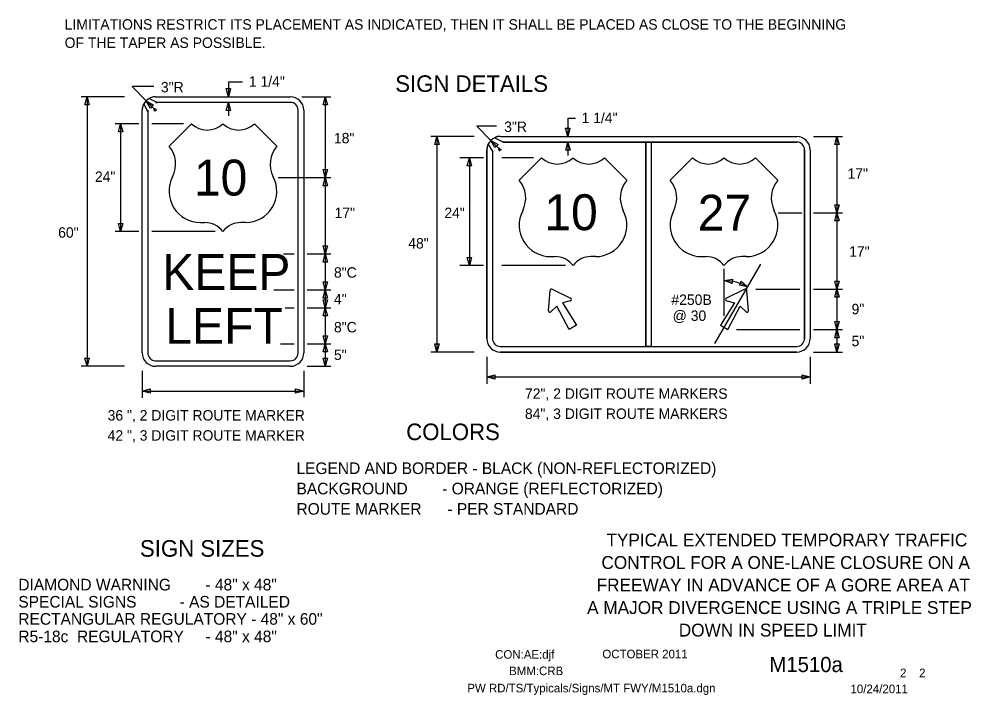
# Model space of a CAD drawing. Extents: x 16335 to 18464, y 5417 to 6974.
# Drawn here: x 17775 to 18464, y 5932 to 6421 of the extents above; entities that cross this region are included whole.
import ezdxf

# ---------------------------------------------------------------- set-up
doc = ezdxf.new("R2010")
doc.units = 0
for name, color, linetype in [('BORDER', 7, 'Continuous'), ('BORDER_SIGNAL_WO', 7, 'Continuous'), ('TRAFFIC_SIGNS_PR', 7, 'Continuous'), ('TYPICAL_EX', 7, 'Continuous'), ('TYPICAL_TEXT_DIMEN_PR', 7, 'Continuous')]:
    doc.layers.add(name, color=color, linetype=linetype)

msp = doc.modelspace()

# ---------------------------------------------------------------- linework, layer by layer
at = {"layer": 'TRAFFIC_SIGNS_PR'}
for p, q in [((17866.33, 6360.97), (17865.33, 6359.46)), ((17875.12, 6360.53), (17869.02, 6363.27)), ((17873.92, 6364.59), (17971.42, 6364.59)), ((17971.42, 6360.53), (17873.92, 6360.53)), ((17864.17, 6179.34), (17864.17, 6354.84)), ((17865.36, 6359.39), (17868.23, 6353.35)), ((17868.23, 6354.84), (17868.23, 6179.34)), ((17977.1, 6179.34), (17977.1, 6354.84)), ((17981.17, 6354.84), (17981.17, 6179.34)), ((18125.39, 6331.84), (18119.16, 6334.86)), ((18123.44, 6335.89), (18337.94, 6335.89)), ((18123.44, 6335.89), (18337.94, 6335.89)), ((18113.69, 6326.14), (18113.69, 6189.64)), ((18113.69, 6189.64), (18113.69, 6326.14)), ((18114.61, 6330.15), (18117.74, 6325.11)), ((18117.75, 6325.09), (18117.75, 6189.64)), ((18117.75, 6325.09), (18117.75, 6189.64)), ((18125.38, 6331.83), (18228.66, 6331.83)), ((18337.94, 6331.83), (18125.38, 6331.83)), ((18228.66, 6331.83), (18228.66, 6183.95)), ((18232.72, 6331.83), (18232.72, 6183.95)), ((18232.72, 6331.83), (18337.94, 6331.83)), ((18343.62, 6326.14), (18343.62, 6280.39)), ((18343.63, 6189.64), (18343.63, 6326.14)), ((18347.69, 6326.14), (18347.69, 6189.64)), ((18347.69, 6326.14), (18347.69, 6189.64)), ((18343.62, 6280.39), (18343.62, 6189.64)), ((18158.29, 6209.75), (18159.44, 6224.47)), ((18160.95, 6225.34), (18174.27, 6218.98)), ((18300.42, 6225.34), (18287.11, 6218.98)), ((18303.08, 6209.75), (18301.94, 6224.47)), ((18123.44, 6183.95), (18337.94, 6183.95)), ((17873.92, 6173.65), (17971.42, 6173.65)), ((18123.44, 6179.89), (18337.94, 6179.89)), ((18337.94, 6179.89), (18123.44, 6179.89)), ((17971.42, 6169.59), (17873.92, 6169.59))]:
    msp.add_line(p, q, dxfattribs=at)
for points in [[(18117.74, 6325.11), (18117.75, 6325.09)], [(18125.38, 6331.83), (18125.36, 6331.84)], [(18174.1, 6217.01), (18168.38, 6215.43), (18178.6, 6199.26), (18173.2, 6196.14), (18164.31, 6213.08), (18160.08, 6208.91)], [(18287.27, 6217.01), (18292.99, 6215.43), (18282.78, 6199.26), (18288.17, 6196.14), (18297.07, 6213.08), (18301.29, 6208.91)]]:
    msp.add_lwpolyline(points, dxfattribs=at)
msp.add_lwpolyline([(18228.66, 6331.83), (18232.72, 6331.83), (18232.72, 6183.95), (18228.66, 6183.95)], close=True, dxfattribs=at)
for centre, radius, start, end in [((17873.92, 6354.84), 9.75, 90, 180), ((17873.33, 6357.01), 7.6, 85.58319, 124.53531), ((17874.52, 6364.95), 4.47, 262.2432, 277.7568), ((17971.42, 6354.84), 9.75, 0, 90), ((17971.42, 6354.84), 5.69, 0, 90), ((17871.2, 6355.43), 7.06, 145.86811, 184.82317), ((17862.77, 6354.1), 5.51, 352.24294, 7.75653), ((18123.44, 6326.14), 9.75, 90, 180), ((18123.44, 6326.14), 9.75, 90, 180), ((18122.76, 6329.33), 6.6, 84.11162, 123.06374), ((18337.94, 6326.14), 9.75, 0, 90), ((18337.94, 6326.14), 9.75, 0, 90), ((18119.82, 6326.85), 6.17, 147.60925, 186.56283), ((18124.38, 6339.01), 7.24, 277.81035, 278.05403), ((18337.94, 6326.14), 5.69, 0, 89.99421), ((18337.94, 6326.14), 5.69, 0, 90), ((18160.5, 6224.38), 1.06, 64.48226, 175.51774), ((18300.88, 6224.38), 1.06, 4.48226, 115.51774), ((18173.81, 6218.02), 1.06, 285.9885, 64.48226), ((18287.56, 6218.02), 1.06, 115.51774, 254.0115), ((18159.35, 6209.67), 1.06, 175.51775, 314.01151), ((18302.03, 6209.67), 1.06, 225.98849, 4.48225), ((18123.44, 6189.64), 9.75, 180, 270), ((18123.44, 6189.64), 9.75, 180, 270), ((18123.44, 6189.64), 5.69, 180, 270), ((18123.44, 6189.64), 5.69, 180, 270), ((18337.94, 6189.64), 9.75, 270, 0), ((18337.94, 6189.64), 5.69, 270, 0), ((18337.94, 6189.64), 9.75, 270, 0), ((18337.94, 6189.64), 5.69, 270, 0), ((17873.92, 6179.34), 9.75, 180, 270), ((17873.92, 6179.34), 5.69, 180, 270), ((17971.42, 6179.34), 5.69, 270, 0), ((17971.42, 6179.34), 9.75, 270, 0)]:
    msp.add_arc(centre, radius, start, end, dxfattribs=at)
at = {"layer": 'TYPICAL_EX'}
for p, q in [((17883.67, 6328.84), (17899.92, 6345.09)), ((17961.67, 6328.84), (17945.42, 6345.09)), ((18137.05, 6304.23), (18153.3, 6320.48)), ((18215.05, 6304.23), (18198.8, 6320.48)), ((18246.33, 6304.23), (18262.58, 6320.48)), ((18324.33, 6304.23), (18308.08, 6320.48)), ((17906.39, 6273.55), (17909.64, 6273.55)), ((17938.94, 6273.55), (17935.69, 6273.55)), ((18159.78, 6248.94), (18163.03, 6248.94)), ((18192.32, 6248.94), (18189.07, 6248.94)), ((18269.05, 6248.94), (18272.3, 6248.94)), ((18301.6, 6248.94), (18298.35, 6248.94))]:
    msp.add_line(p, q, dxfattribs=at)
for centre, radius, start, end in [((17911.29, 6356.93), 16.42, 226.14041, 313.85958), ((17934.04, 6356.93), 16.42, 226.14042, 313.85959), ((17868.26, 6315.83), 20.16, 333.09768, 40.19361), ((17977.07, 6315.83), 20.16, 139.80639, 206.90233), ((18164.68, 6332.32), 16.42, 226.14041, 313.85958), ((18187.42, 6332.32), 16.42, 226.14042, 313.85959), ((18273.95, 6332.32), 16.42, 226.14041, 313.85958), ((18296.7, 6332.32), 16.42, 226.14042, 313.85959), ((17906.43, 6296.27), 22.73, 152.6698, 269.90132), ((17938.9, 6296.27), 22.73, 270.09868, 27.3302), ((18121.65, 6291.22), 20.16, 333.09768, 40.19361), ((18230.45, 6291.22), 20.16, 139.80639, 206.90233), ((18230.93, 6291.22), 20.16, 333.09768, 40.19361), ((18339.73, 6291.22), 20.16, 139.80639, 206.90233), ((18159.82, 6271.66), 22.73, 152.6698, 269.90132), ((18192.28, 6271.66), 22.73, 270.09868, 27.3302), ((18269.09, 6271.66), 22.73, 152.6698, 269.90132), ((18301.56, 6271.66), 22.73, 270.09868, 27.3302), ((17909.68, 6257.27), 16.28, 37.1038, 90.13853), ((17935.65, 6257.27), 16.28, 89.86147, 142.8962), ((18163.07, 6232.66), 16.28, 37.1038, 90.13853), ((18189.03, 6232.66), 16.28, 89.86147, 142.8962), ((18272.35, 6232.66), 16.28, 37.1038, 90.13853), ((18298.31, 6232.66), 16.28, 89.86147, 142.8962)]:
    msp.add_arc(centre, radius, start, end, dxfattribs=at)
at = {"layer": 'TYPICAL_TEXT_DIMEN_PR'}
for p, q in [((17926.64, 6375.35), (17926.64, 6364.59)), ((17926.64, 6375.35), (17936.74, 6375.35)), ((17872.54, 6371.87), (17856.88, 6371.87)), ((17856.88, 6371.87), (17867.12, 6361.64)), ((17926.64, 6364.59), (17925.07, 6370.45)), ((17925.07, 6370.45), (17926.64, 6370.45)), ((17926.64, 6370.45), (17928.21, 6370.45)), ((17928.21, 6370.45), (17926.64, 6364.59)), ((17851.34, 6364.59), (17820.04, 6364.59)), ((17822.81, 6358.73), (17824.38, 6364.59)), ((17824.38, 6364.59), (17824.38, 6169.59)), ((17824.38, 6364.59), (17825.95, 6358.73)), ((17867.12, 6361.64), (17873.67, 6355.08)), ((17870.15, 6356.38), (17867.12, 6361.64)), ((17867.12, 6361.64), (17872.37, 6358.6)), ((17925.12, 6354.67), (17926.69, 6360.53)), ((17926.69, 6360.53), (17926.69, 6350.78)), ((17926.69, 6360.53), (17928.26, 6354.67)), ((17979.71, 6364.59), (18000.67, 6364.59)), ((17995.2, 6358.73), (17996.77, 6364.59)), ((17996.77, 6364.59), (17996.77, 6306.09)), ((17996.77, 6364.59), (17998.34, 6358.73)), ((17824.38, 6358.73), (17822.81, 6358.73)), ((17825.95, 6358.73), (17824.38, 6358.73)), ((17871.26, 6357.49), (17870.15, 6356.38)), ((17872.37, 6358.6), (17871.26, 6357.49)), ((17872.47, 6355.08), (17874.88, 6355.08)), ((17873.67, 6353.87), (17873.67, 6356.29)), ((17926.69, 6354.67), (17925.12, 6354.67)), ((17928.26, 6354.67), (17926.69, 6354.67)), ((17996.77, 6358.73), (17995.2, 6358.73)), ((17998.34, 6358.73), (17996.77, 6358.73)), ((18172.3, 6349.04), (18172.3, 6335.89)), ((18172.3, 6349.04), (18177.82, 6349.04)), ((17861.79, 6345.09), (17844.67, 6345.09)), ((17846.99, 6339.23), (17848.56, 6345.09)), ((17848.56, 6339.23), (17846.99, 6339.23)), ((17848.56, 6345.09), (17848.56, 6267.09)), ((17848.56, 6345.09), (17850.13, 6339.23)), ((17850.13, 6339.23), (17848.56, 6339.23)), ((17894.03, 6345.09), (17871.16, 6345.09)), ((18120.58, 6343.18), (18106.4, 6343.18)), ((18106.4, 6343.18), (18116.55, 6333.03)), ((18172.3, 6335.89), (18170.72, 6341.75)), ((18170.72, 6341.75), (18172.3, 6341.75)), ((18172.3, 6341.75), (18173.87, 6341.75)), ((18173.87, 6341.75), (18172.3, 6335.89)), ((18104.46, 6335.89), (18073.16, 6335.89)), ((18075.93, 6330.03), (18077.5, 6335.89)), ((18077.5, 6335.89), (18077.5, 6179.89)), ((18077.5, 6335.89), (18079.07, 6330.03)), ((18116.55, 6333.03), (18123.2, 6326.38)), ((18119.58, 6327.77), (18116.55, 6333.03)), ((18116.55, 6333.03), (18121.81, 6329.99)), ((18350.06, 6335.89), (18371.02, 6335.89)), ((18365.55, 6330.03), (18367.12, 6335.89)), ((18367.12, 6335.89), (18367.12, 6280.64)), ((18367.12, 6335.89), (18368.69, 6330.03)), ((18077.5, 6330.03), (18075.93, 6330.03)), ((18079.07, 6330.03), (18077.5, 6330.03)), ((18120.7, 6328.88), (18119.58, 6327.77)), ((18121.81, 6329.99), (18120.7, 6328.88)), ((18121.99, 6326.38), (18124.41, 6326.38)), ((18123.2, 6325.17), (18123.2, 6327.59)), ((18170.77, 6325.97), (18172.34, 6331.83)), ((18170.77, 6325.97), (18172.34, 6331.83)), ((18172.34, 6325.97), (18170.77, 6325.97)), ((18172.34, 6325.97), (18170.77, 6325.97)), ((18172.34, 6331.83), (18172.34, 6322.08)), ((18172.34, 6331.83), (18173.92, 6325.97)), ((18172.34, 6331.83), (18173.92, 6325.97)), ((18173.92, 6325.97), (18172.34, 6325.97)), ((18173.92, 6325.97), (18172.34, 6325.97)), ((18367.12, 6330.03), (18365.55, 6330.03)), ((18368.69, 6330.03), (18367.12, 6330.03)), ((18111.31, 6320.48), (18094.19, 6320.48)), ((18099.48, 6314.62), (18101.06, 6320.48)), ((18101.06, 6320.48), (18101.06, 6242.48)), ((18101.06, 6320.48), (18102.63, 6314.62)), ((18147.42, 6320.48), (18124.54, 6320.48)), ((17996.77, 6306.09), (17995.2, 6311.95)), ((17995.2, 6311.95), (17996.77, 6311.95)), ((17996.77, 6311.95), (17998.34, 6311.95)), ((17998.34, 6311.95), (17996.77, 6306.09)), ((18101.06, 6314.62), (18099.48, 6314.62)), ((18102.63, 6314.62), (18101.06, 6314.62)), ((17962.56, 6306.09), (18000.67, 6306.09)), ((17995.2, 6300.23), (17996.77, 6306.09)), ((17996.77, 6306.09), (17996.77, 6250.84)), ((17996.77, 6306.09), (17998.34, 6300.23)), ((17996.77, 6300.23), (17995.2, 6300.23)), ((17998.34, 6300.23), (17996.77, 6300.23)), ((18367.12, 6280.64), (18365.55, 6286.5)), ((18365.55, 6286.5), (18367.12, 6286.5)), ((18367.12, 6286.5), (18368.69, 6286.5)), ((18368.69, 6286.5), (18367.12, 6280.64)), ((18324.5, 6280.64), (18341.65, 6280.64)), ((18350.06, 6280.64), (18371.02, 6280.64)), ((18365.55, 6274.78), (18367.12, 6280.64)), ((18367.12, 6280.64), (18367.12, 6225.39)), ((18367.12, 6280.64), (18368.69, 6274.78)), ((17848.56, 6267.09), (17846.99, 6272.95)), ((17846.99, 6272.95), (17848.56, 6272.95)), ((17848.56, 6272.95), (17850.13, 6272.95)), ((17850.13, 6272.95), (17848.56, 6267.09)), ((18367.12, 6274.78), (18365.55, 6274.78)), ((18368.69, 6274.78), (18367.12, 6274.78)), ((17861.79, 6267.09), (17844.67, 6267.09)), ((17917.16, 6267.09), (17871.16, 6267.09)), ((17996.77, 6250.84), (17995.2, 6256.7)), ((17995.2, 6256.7), (17996.77, 6256.7)), ((17996.77, 6256.7), (17998.34, 6256.7)), ((17998.34, 6256.7), (17996.77, 6250.84)), ((17966.49, 6250.84), (17974.17, 6250.84)), ((17983.54, 6250.84), (18000.67, 6250.84)), ((17995.2, 6244.98), (17996.77, 6250.84)), ((17996.77, 6250.84), (17996.77, 6224.84)), ((17996.77, 6250.84), (17998.34, 6244.98)), ((17996.77, 6244.98), (17995.2, 6244.98)), ((17998.34, 6244.98), (17996.77, 6244.98)), ((18111.31, 6242.48), (18094.19, 6242.48)), ((18101.06, 6242.48), (18099.48, 6248.34)), ((18099.48, 6248.34), (18101.06, 6248.34)), ((18101.06, 6248.34), (18102.63, 6248.34)), ((18102.63, 6248.34), (18101.06, 6242.48)), ((18170.54, 6242.48), (18124.54, 6242.48)), ((18278.72, 6185.99), (18311.96, 6243.58)), ((18285.48, 6206.15), (18285.48, 6240.14)), ((17996.77, 6224.84), (17995.2, 6230.7)), ((17995.2, 6230.7), (17996.77, 6230.7)), ((17996.77, 6230.7), (17998.34, 6230.7)), ((17998.34, 6230.7), (17996.77, 6224.84)), ((18285.51, 6231.59), (18291.5, 6232.55)), ((18291.17, 6229.42), (18285.51, 6231.59)), ((18291.34, 6230.98), (18291.17, 6229.42)), ((18291.5, 6232.55), (18291.34, 6230.98)), ((18296.49, 6228.26), (18297.17, 6229.68)), ((18297.17, 6229.68), (18297.86, 6231.09)), ((18297.86, 6231.09), (18302.46, 6227.13)), ((18367.12, 6225.39), (18365.55, 6231.25)), ((18365.55, 6231.25), (18367.12, 6231.25)), ((18367.12, 6231.25), (18368.69, 6231.25)), ((18368.69, 6231.25), (18367.12, 6225.39)), ((17959.48, 6224.84), (17974.17, 6224.84)), ((17983.54, 6224.84), (18000.67, 6224.84)), ((17995.2, 6218.98), (17996.77, 6224.84)), ((17996.77, 6224.84), (17996.77, 6211.84)), ((17996.77, 6224.84), (17998.34, 6218.98)), ((18302.46, 6227.13), (18296.49, 6228.26)), ((18308.43, 6225.39), (18340.3, 6225.39)), ((18350.06, 6225.39), (18371.02, 6225.39)), ((18365.55, 6219.53), (18367.12, 6225.39)), ((18367.12, 6225.39), (18367.12, 6196.14)), ((18367.12, 6225.39), (18368.69, 6219.53)), ((17996.77, 6218.98), (17995.2, 6218.98)), ((17996.77, 6211.84), (17995.2, 6217.7)), ((17995.2, 6217.7), (17996.77, 6217.7)), ((17998.34, 6218.98), (17996.77, 6218.98)), ((17996.77, 6217.7), (17998.34, 6217.7)), ((17998.34, 6217.7), (17996.77, 6211.84)), ((18367.12, 6219.53), (18365.55, 6219.53)), ((18368.69, 6219.53), (18367.12, 6219.53)), ((17967.83, 6211.84), (17974.17, 6211.84)), ((17983.54, 6211.84), (18000.67, 6211.84)), ((17995.2, 6205.98), (17996.77, 6211.84)), ((17996.77, 6211.84), (17996.77, 6185.84)), ((17996.77, 6211.84), (17998.34, 6205.98)), ((17996.77, 6205.98), (17995.2, 6205.98)), ((17998.34, 6205.98), (17996.77, 6205.98)), ((18367.12, 6196.14), (18365.55, 6202)), ((18365.55, 6202), (18367.12, 6202)), ((18367.12, 6202), (18368.69, 6202)), ((18368.69, 6202), (18367.12, 6196.14)), ((18294.29, 6196.14), (18340.3, 6196.14)), ((18350.06, 6196.14), (18371.02, 6196.14)), ((18365.55, 6190.28), (18367.12, 6196.14)), ((18367.12, 6196.14), (18367.12, 6179.89)), ((18367.12, 6196.14), (18368.69, 6190.28)), ((17996.77, 6185.84), (17995.2, 6191.7)), ((17995.2, 6191.7), (17996.77, 6191.7)), ((17996.77, 6191.7), (17998.34, 6191.7)), ((17998.34, 6191.7), (17996.77, 6185.84)), ((18367.12, 6190.28), (18365.55, 6190.28)), ((18368.69, 6190.28), (18367.12, 6190.28)), ((17964.33, 6185.84), (17974.17, 6185.84)), ((17983.54, 6185.84), (18000.67, 6185.84)), ((17995.2, 6179.98), (17996.77, 6185.84)), ((17996.77, 6185.84), (17996.77, 6169.59)), ((17996.77, 6185.84), (17998.34, 6179.98)), ((18077.5, 6179.89), (18075.93, 6185.75)), ((18075.93, 6185.75), (18077.5, 6185.75)), ((18077.5, 6185.75), (18079.07, 6185.75)), ((18079.07, 6185.75), (18077.5, 6179.89)), ((18367.12, 6179.89), (18365.55, 6185.75)), ((18365.55, 6185.75), (18367.12, 6185.75)), ((18367.12, 6185.75), (18368.69, 6185.75)), ((18368.69, 6185.75), (18367.12, 6179.89)), ((17824.38, 6169.59), (17822.81, 6175.45)), ((17822.81, 6175.45), (17824.38, 6175.45)), ((17824.38, 6175.45), (17825.95, 6175.45)), ((17825.95, 6175.45), (17824.38, 6169.59)), ((17996.77, 6179.98), (17995.2, 6179.98)), ((17996.77, 6169.59), (17995.2, 6175.45)), ((17995.2, 6175.45), (17996.77, 6175.45)), ((17998.34, 6179.98), (17996.77, 6179.98)), ((17996.77, 6175.45), (17998.34, 6175.45)), ((17998.34, 6175.45), (17996.77, 6169.59)), ((18104.46, 6179.89), (18073.16, 6179.89)), ((18113.69, 6176.55), (18113.69, 6156.99)), ((18347.69, 6176.55), (18347.69, 6156.99)), ((18350.06, 6179.89), (18367.19, 6179.89)), ((18350.06, 6179.89), (18371.02, 6179.89)), ((18350.06, 6179.89), (18367.19, 6179.89)), ((17851.34, 6169.59), (17820.04, 6169.59)), ((17983.54, 6169.59), (18000.67, 6169.59)), ((17864.17, 6166.25), (17864.17, 6146.89)), ((17981.17, 6166.25), (17981.17, 6147.35)), ((18113.69, 6161.92), (18119.55, 6163.49)), ((18113.69, 6161.92), (18347.69, 6161.92)), ((18119.55, 6160.35), (18113.69, 6161.92)), ((18119.55, 6163.49), (18119.55, 6161.92)), ((18119.55, 6161.92), (18119.55, 6160.35)), ((18341.83, 6161.92), (18341.83, 6163.49)), ((18341.83, 6163.49), (18347.69, 6161.92)), ((18347.69, 6161.92), (18341.83, 6160.35)), ((18341.83, 6160.35), (18341.83, 6161.92)), ((17864.17, 6151.62), (17870.03, 6153.19)), ((17870.03, 6153.19), (17870.03, 6151.62)), ((17975.3, 6151.62), (17975.3, 6153.19)), ((17975.3, 6153.19), (17981.17, 6151.62)), ((17864.17, 6151.62), (17981.17, 6151.62)), ((17870.03, 6150.05), (17864.17, 6151.62)), ((17870.03, 6151.62), (17870.03, 6150.05)), ((17981.17, 6151.62), (17975.3, 6150.05)), ((17975.3, 6150.05), (17975.3, 6151.62))]:
    msp.add_line(p, q, dxfattribs=at)
msp.add_arc((18285.67, 6197.15), 34.39, 60.74521, 90.32117, dxfattribs=at)

# ---------------------------------------------------------------- texts
at = {"layer": 'BORDER'}
for s, p in [('TYPICAL EXTENDED TEMPORARY TRAFFIC', (18200.26, 6039.3)), ('CONTROL FOR A ONE-LANE CLOSURE ON A', (18196.63, 6023)), ('FREEWAY IN ADVANCE OF A GORE AREA AT', (18193.13, 6006.7)), ('A MAJOR DIVERGENCE USING A TRIPLE STEP', (18186.26, 5990.4)), ('DOWN IN SPEED LIMIT', (18252.63, 5974.11))]:
    msp.add_text(s, height=9.3, dxfattribs=at).set_placement(p)
at = {"layer": 'BORDER_SIGNAL_WO'}
for s, height, p in [('CON:AE:djf  ', 6.2, (18119.69, 5958.06)), ('    OCTOBER 2011    ', 6.2, (18188.08, 5958.34)), ('    M1510a   ', 11, (18301.86, 5948.38)), ('BMM:CRB   ', 6.2, (18129.81, 5946.17)), (' 2    2 ', 6.2, (18410.45, 5944.7)), ('PW RD/TS/Typicals/Signs/MT FWY/M1510a.dgn      ', 6.2, (18099.55, 5933.71)), ('10/24/2011    ', 6.2, (18376.93, 5933.13))]:
    msp.add_text(s, height=height, dxfattribs=at).set_placement(p)
at = {"layer": 'TRAFFIC_SIGNS_PR'}
for s, p in [('10', (17901.64, 6293.09)), ('10', (18155.29, 6268.02)), ('27', (18266.29, 6267.66)), ('KEEP', (17878.77, 6224.84)), ('LEFT', (17881, 6185.84))]:
    msp.add_text(s, height=26, dxfattribs=at).set_placement(p)
at = {"layer": 'TYPICAL_TEXT_DIMEN_PR'}
for s, height, p in [('LIMITATIONS RESTRICT ITS PLACEMENT AS INDICATED, THEN IT SHALL BE PLACED AS CLOSE TO THE BEGINNING', 7.56, (17808.1, 6413.11)), ('OF THE TAPER AS POSSIBLE.', 7.56, (17808.1, 6399.88)), ('SIGN DETAILS', 12, (18047.39, 6368.06)), ('3"R', 7.55, (17877.8, 6367.75)), ('1 1/4"', 7.55, (17941.44, 6371.85)), ('1 1/4"', 7.55, (18182.22, 6345.47)), ('3"R', 7.55, (18126.22, 6339.1)), ('18"', 7.55, (18003.01, 6330.86)), ('17"', 7.55, (18374.7, 6305.25)), ('24"', 7.55, (17830.01, 6302.97)), ('17"', 7.55, (18003.46, 6276.81)), ('24"', 7.55, (18082.91, 6276.81)), ('60"', 7.55, (17803.41, 6262.61)), ('48"', 7.55, (18056.8, 6254.79)), ('17"', 7.55, (18375.9, 6248.89)), ('8"C', 7.55, (18003.04, 6233.7)), ('4" ', 7.55, (18003.04, 6214.44)), ('#250B', 7.55, (18247.25, 6213.98)), ('9"', 7.55, (18377.68, 6207.24)), ('@ 30', 7.55, (18248.19, 6202.43)), ('8"C', 7.55, (18003.04, 6194.11)), ('5"', 7.55, (18377.68, 6184.14)), ('5" ', 7.55, (18003.04, 6174.14)), ('72", 2 DIGIT ROUTE MARKERS', 7.55, (18141.27, 6146.06)), ('84", 3 DIGIT ROUTE MARKERS', 7.55, (18141.27, 6131.51)), ('36 ", 2 DIGIT ROUTE MARKER', 7.55, (17839.21, 6130.36)), ('COLORS', 12, (18055.33, 6116.17)), ('42 ", 3 DIGIT ROUTE MARKER', 7.55, (17839.21, 6115.81)), ('LEGEND AND BORDER - BLACK (NON-REFLECTORIZED)', 8.4, (17975.9, 6091.65)), ('BACKGROUND        - ORANGE (REFLECTORIZED)', 8.4, (17975.9, 6076.94)), ('ROUTE MARKER      - PER STANDARD', 8.4, (17975.9, 6062.24)), ('SIGN SIZES', 12, (17862.62, 6031.84)), ('DIAMOND WARNING        - 48" x 48"', 8.4, (17774.58, 6007.44)), ('SPECIAL SIGNS          - AS DETAILED', 8.4, (17774.58, 5995.04)), ('RECTANGULAR REGULATORY - 48" x 60"', 8.4, (17774.58, 5982.64)), ('R5-18c  REGULATORY     - 48" x 48"', 8.4, (17774.58, 5969.99))]:
    msp.add_text(s, height=height, dxfattribs=at).set_placement(p)

doc.saveas('drawing.dxf')
